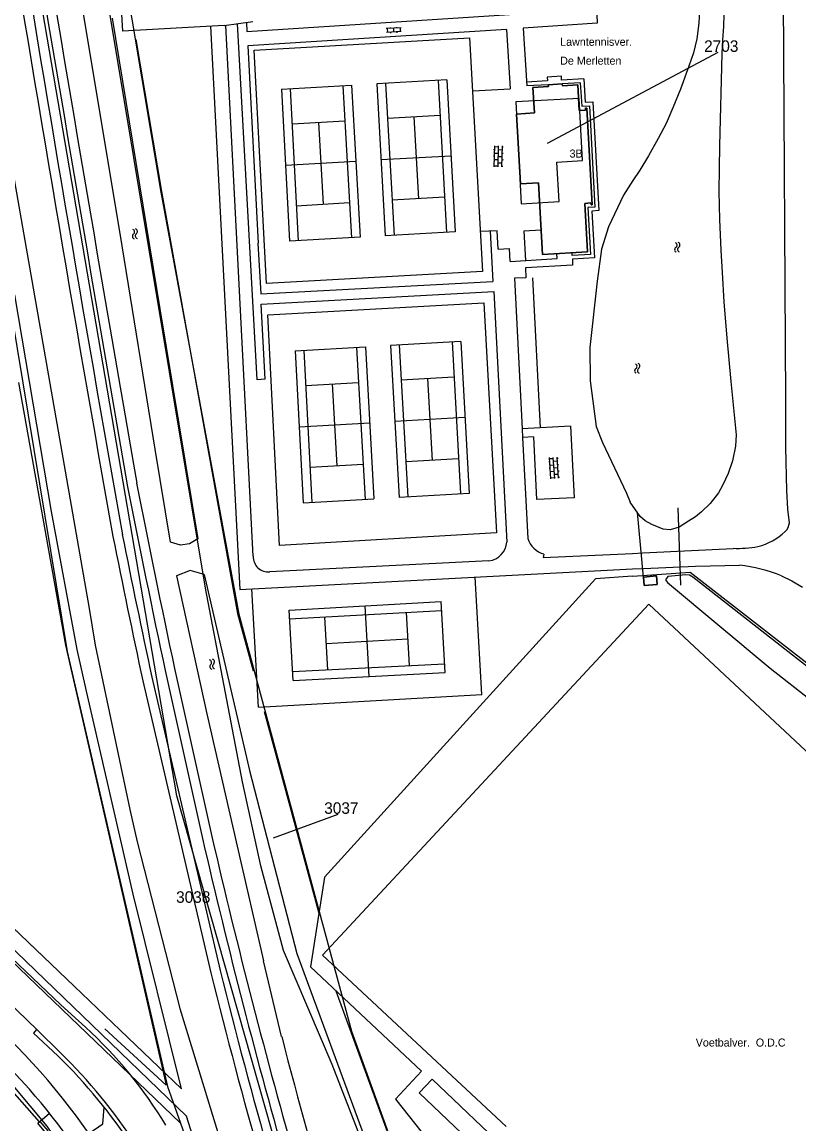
# Model space of a CAD drawing. Extents: x 148816 to 151297, y 399515 to 402500.
# Drawn here: x 149404.6 to 149526, y 400552.9 to 400725 of the extents above; entities that cross this region are included whole.
import ezdxf

# ---------------------------------------------------------------- set-up
doc = ezdxf.new("R2010")
doc.units = 0
for name, color, linetype in [('B01 Hoofdgebouw  [D] Norm', 7, 'Continuous'), ('B01 Hoofdgebouw  [T] Norm', 7, 'Continuous'), ('B01 hoofgebouw', 7, 'Continuous'), ('B03 Overig opstal  [D] Norm', 7, 'Continuous'), ('G01 perceelsgrens', 7, 'Continuous'), ('Q01 Spoorrail  [D] Norm', 7, 'Continuous'), ('Q21 Lichtmast  Gem', 7, 'Continuous'), ('S02 Open verharding  Norm', 7, 'Continuous'), ('S05 Water  Norm', 7, 'Continuous'), ('T01 Muur  [D] Gem', 7, 'Continuous'), ('T01 Muur  [T] Gem', 7, 'Continuous'), ('T04 Haag heg  [D] Gem', 7, 'Continuous'), ('T09 Insteek water  [T] Norm', 7, 'Continuous'), ('V00 Kant verharding algemeen  [T] Norm', 7, 'Continuous'), ('V00 Kant verharding algemeen secundair  [T] Gem', 7, 'Continuous'), ('V06 Kant onverhard  [T] Gem', 7, 'Continuous'), ('W10 Duiker  [T] Gem', 7, 'Continuous'), ('Z01 perceelnummer', 7, 'Continuous'), ('Z02 Huisnummer  [Tekst] Norm', 7, 'Continuous'), ('Z19 Overige Tekst  [Tekst] Gem', 7, 'Continuous')]:
    doc.layers.add(name, color=color, linetype=linetype)

msp = doc.modelspace()

# ---------------------------------------------------------------- linework, layer by layer
at = {"layer": 'B01 Hoofdgebouw  [D] Norm'}
msp.add_lwpolyline([(149468.7, 400559.93), (149477.56, 400551.5), (149475.54, 400549.38), (149466.68, 400557.81)], close=True, dxfattribs=at)
at = {"layer": 'B01 Hoofdgebouw  [T] Norm'}
for p, q in [((149492.98, 400689.1), (149485.94, 400688.7)), ((149503.76, 400638.51), (149501.71, 400638.32)), ((149501.71, 400638.32), (149501.83, 400637)), ((149503.88, 400637.19), (149503.76, 400638.51)), ((149501.83, 400637), (149503.88, 400637.19))]:
    msp.add_line(p, q, dxfattribs=at)
for points in [[(149492.87, 400711.54), (149492.65, 400711.53), (149492.67, 400711.24), (149491.69, 400711.18), (149491.46, 400715.16), (149489.05, 400715.02), (149489.03, 400715.32), (149486.86, 400715.2), (149486.88, 400714.9), (149484.45, 400714.76), (149484.68, 400710.79), (149481.88, 400710.62), (149482.5, 400699.73), (149485.3, 400699.89), (149485.94, 400688.7), (149492.98, 400689.1)], [(149485.94, 400688.7), (149492.98, 400689.1), (149492.54, 400696.67), (149493.52, 400696.73), (149493.54, 400696.44), (149493.72, 400696.45), (149492.87, 400711.54)]]:
    msp.add_lwpolyline(points, dxfattribs=at)
at = {"layer": 'B01 hoofgebouw'}
for points in [[(149491.69, 400711.18), (149492.67, 400711.24), (149492.67, 400711.59), (149492.87, 400711.54), (149493.72, 400696.45), (149493.54, 400696.44), (149493.52, 400696.73), (149492.54, 400696.67), (149492.98, 400689.1), (149485.94, 400688.7), (149485.3, 400699.89), (149482.5, 400699.73), (149481.88, 400710.62), (149484.68, 400710.79), (149484.45, 400714.76), (149486.88, 400714.9), (149486.86, 400715.2), (149489.03, 400715.32), (149489.05, 400715.02), (149491.46, 400715.16), (149491.69, 400711.18)], [(149501.71, 400638.32), (149503.76, 400638.51), (149503.88, 400637.19), (149501.83, 400637), (149501.71, 400638.32)]]:
    msp.add_lwpolyline(points, dxfattribs=at)
at = {"layer": 'B03 Overig opstal  [D] Norm'}
msp.add_line((149407.42, 400553.33), (149408.92, 400554.61), dxfattribs=at)
at = {"layer": 'G01 perceelsgrens'}
for points in [[(149474.3, 400500), (149465.62, 400529.89), (149453.09, 400562.24), (149445.47, 400580.02), (149441.93, 400593.24), (149439.07, 400606.36), (149433.29, 400636.6), (149410.86, 400771.43), (149399.43, 400842.23), (149379.26, 400968.4), (149379, 400970.86), (149375.68, 400970.26), (149373.64, 400982.49), (149377.7, 400983.23), (149377.26, 400987.35)], [(149380.85, 400976.67), (149402.17, 400842.5), (149426.33, 400698.43), (149438.5, 400632.51), (149456.12, 400567.45), (149480.52, 400500)], [(149492.2, 400703.36), (149491.67, 400713.05), (149481.76, 400712.51), (149482.63, 400696.62), (149488.56, 400696.97), (149488.2, 400703.12), (149492.2, 400703.36)], [(149401.28, 400689.77), (149411.69, 400626.68), (149427.38, 400558.77), (149429.39, 400553.07)], [(149347.22, 400631.91), (149429.39, 400553.07)], [(149403.2, 400558.96), (149408.53, 400552.62), (149411.03, 400548.92)], [(149429.39, 400553.07), (149448.02, 400500)]]:
    msp.add_lwpolyline(points, dxfattribs=at)
at = {"layer": 'Q01 Spoorrail  [D] Norm'}
for p, q in [((149424.93, 400622.69), (149435.58, 400576.88)), ((149427.01, 400623.72), (149432.83, 400597.5)), ((149428.47, 400624.05), (149434.3, 400597.83)), ((149423.52, 400622.14), (149434.12, 400576.52)), ((149401.92, 400559.42), (149407.33, 400553.28))]:
    msp.add_line(p, q, dxfattribs=at)
for centre, radius, start, end in [((156405.27, 401884.74), 7094.13, 189.218769, 190.064919), ((165820.47, 403491.79), 16643.33, 189.484339, 189.821758), ((165820.47, 403491.79), 16641.83, 189.485686, 189.821758), ((156405.27, 401884.74), 7095.63, 189.218769, 190.064919), ((151062.51, 400973.51), 1672.49, 191.05884, 192.0799), ((151062.51, 400973.51), 1670.99, 191.05884, 192.07174), ((150862.74, 400932.64), 1470.84, 191.27964, 192.16518), ((150862.74, 400932.64), 1472.34, 191.27964, 192.17434), ((150428.26, 400826.81), 1021.49, 192.97285, 195.97777), ((150428.26, 400826.81), 1019.99, 192.97285, 195.97777), ((150353.21, 400806.24), 947.36, 194.03323, 197.71533), ((150353.21, 400806.24), 945.86, 194.03323, 197.71533)]:
    msp.add_arc(centre, radius, start, end, dxfattribs=at)
at = {"layer": 'Q21 Lichtmast  Gem'}
msp.add_lwpolyline([(149831.23, 399977.82), (149652.8, 400166.23), (149577.93, 400264.8), (149509.93, 400379.6), (149457.52, 400503.12), (149428.83, 400604.19), (149365.19, 400976.02), (149329.8, 401182.82), (149252.91, 401632.09)], dxfattribs=at)
at = {"layer": 'S02 Open verharding  Norm'}
for p, q in [((149463.85, 400724.09), (149461.55, 400723.95)), ((149462.2, 400723.99), (149462.19, 400724.14)), ((149462.74, 400723.42), (149462.7, 400724.02)), ((149463.2, 400724.05), (149463.19, 400724.2)), ((149463.7, 400724.08), (149463.73, 400723.48)), ((149463.88, 400723.49), (149461.59, 400723.35)), ((149461.7, 400723.96), (149461.74, 400723.36)), ((149462.24, 400723.24), (149462.24, 400723.39)), ((149463.24, 400723.3), (149463.23, 400723.45)), ((149478.4, 400702.38), (149478.48, 400705.67)), ((149478.48, 400705.53), (149479.08, 400705.51)), ((149479.01, 400702.36), (149479.08, 400705.66)), ((149479.61, 400702.35), (149479.68, 400705.65)), ((149479.68, 400705.5), (149479.83, 400705.49)), ((149478.44, 400704.03), (149478.29, 400704.03)), ((149478.46, 400705.03), (149478.32, 400705.03)), ((149478.43, 400703.53), (149479.03, 400703.51)), ((149478.45, 400704.53), (149479.05, 400704.51)), ((149479.04, 400704.01), (149479.64, 400704)), ((149479.66, 400705), (149479.07, 400705.01)), ((149479.63, 400703.5), (149479.78, 400703.49)), ((149479.65, 400704.5), (149479.8, 400704.49)), ((149478.42, 400703.03), (149478.27, 400703.03)), ((149478.41, 400702.53), (149479.01, 400702.51)), ((149479.02, 400703.01), (149479.62, 400703)), ((149479.61, 400702.5), (149479.76, 400702.49)), ((149487.26, 400653.68), (149487.04, 400656.97)), ((149487.86, 400653.72), (149487.64, 400657.01)), ((149488.46, 400653.76), (149488.24, 400657.05)), ((149487.08, 400656.32), (149486.93, 400656.31)), ((149487.15, 400655.32), (149487, 400655.31)), ((149487.05, 400656.82), (149487.65, 400656.86)), ((149487.12, 400655.82), (149487.72, 400655.86)), ((149488.28, 400656.4), (149487.68, 400656.36)), ((149487.75, 400655.36), (149488.35, 400655.41)), ((149488.25, 400656.9), (149488.4, 400656.91)), ((149488.32, 400655.91), (149488.46, 400655.92)), ((149487.22, 400654.33), (149487.07, 400654.32)), ((149487.18, 400654.83), (149487.78, 400654.87)), ((149487.25, 400653.83), (149487.85, 400653.87)), ((149487.82, 400654.37), (149488.42, 400654.41)), ((149488.38, 400654.91), (149488.53, 400654.92)), ((149488.45, 400653.91), (149488.6, 400653.92))]:
    msp.add_line(p, q, dxfattribs=at)
at = {"layer": 'S05 Water  Norm'}
for centre, start, end in [((149422.31, 400691.53), 126.4891, 250.3441), ((149421.81, 400692.21), 306.4891, 70.3441), ((149422.76, 400691.6), 126.4891, 250.3441), ((149422.25, 400692.28), 306.4891, 70.3441), ((149507.02, 400689.43), 123.6187, 247.4737), ((149506.55, 400690.14), 303.6187, 67.4737), ((149507.47, 400689.47), 123.6187, 247.4737), ((149507, 400690.18), 303.6187, 67.4737), ((149500.77, 400670.53), 123.6187, 247.4737), ((149500.29, 400671.23), 303.6187, 67.4737), ((149501.21, 400670.57), 123.6187, 247.4737), ((149500.74, 400671.28), 303.6187, 67.4737), ((149433.84, 400624.99), 310.7816, 74.6367), ((149434.39, 400624.34), 130.7816, 254.6367), ((149434.28, 400625.09), 310.7816, 74.6367), ((149434.83, 400624.44), 130.7816, 254.6367)]:
    msp.add_arc(centre, 0.425, start, end, dxfattribs=at)
at = {"layer": 'T01 Muur  [D] Gem'}
msp.add_line((149490.92, 400650.68), (149485.03, 400650.42), dxfattribs=at)
at = {"layer": 'T01 Muur  [T] Gem'}
msp.add_lwpolyline([(149407.42, 400553.33), (149408.68, 400551.86), (149408.36, 400551.58), (149407.1, 400553.05)], close=True, dxfattribs=at)
at = {"layer": 'T04 Haag heg  [D] Gem'}
for p, q in [((149418.3, 400760.19), (149420.33, 400723.57)), ((149493.36, 400750), (149494.49, 400724.81)), ((149436.21, 400724.45), (149420.33, 400723.57)), ((149436.21, 400724.45), (149440.71, 400725.05)), ((149422.44, 400722.26), (149426.42, 400698.53)), ((149426.42, 400698.53), (149438.31, 400632.66)), ((149484.39, 400685.05), (149485.56, 400661.62)), ((149404.1, 400668.72), (149411.41, 400627.67)), ((149501.71, 400638.32), (149500.79, 400648.43)), ((149494.21, 400638.03), (149451.92, 400591.46)), ((149476.49, 400619.99), (149475.45, 400638.32)), ((149500, 400638.49), (149494.21, 400638.03)), ((149441.6, 400618), (149440.54, 400636.51)), ((149438.31, 400632.66), (149440.76, 400623.67)), ((149411.41, 400627.67), (149427.16, 400558.98)), ((149441.6, 400618), (149476.49, 400619.99)), ((149442.47, 400617.36), (149451.03, 400585.85)), ((149451.92, 400591.46), (149449.7, 400577.45)), ((149449.7, 400577.45), (149467.04, 400561.2)), ((149453.67, 400573.73), (149466.1, 400539.69)), ((149427.16, 400558.98), (149417.6, 400567.79)), ((149467.04, 400561.2), (149462.98, 400556.79)), ((149462.98, 400556.79), (149472.31, 400545.12))]:
    msp.add_line(p, q, dxfattribs=at)
for points in [[(149440.91, 400720.59), (149474.55, 400722.49), (149476.6, 400686.04), (149442.82, 400684.14)], [(149443.05, 400679.25), (149476.81, 400681.16), (149478.76, 400645.21), (149444.85, 400643.28)]]:
    msp.add_lwpolyline(points, close=True, dxfattribs=at)
msp.add_lwpolyline([(149500.04, 400638.49), (149509, 400639.11), (149576.33, 400586.78), (149574.66, 400584.2)], dxfattribs=at)
at = {"layer": 'T09 Insteek water  [T] Norm'}
for p, q in [((149394.73, 400749.75), (149409, 400668.53)), ((149420.27, 400690.04), (149414.18, 400726.64)), ((149418.7, 400725.56), (149426.17, 400680.22)), ((149500.06, 400700.24), (149498.6, 400697.95)), ((149498.6, 400697.95), (149496.27, 400692.98)), ((149496.27, 400692.98), (149495.18, 400689.53)), ((149425.46, 400658.28), (149420.27, 400690.04)), ((149495.18, 400689.53), (149494.48, 400684.54)), ((149494.48, 400684.54), (149493.35, 400674.18)), ((149409.23, 400648.57), (149403.52, 400682.4)), ((149426.17, 400680.22), (149432.13, 400644.28)), ((149493.35, 400674.18), (149493.4, 400668.96)), ((149493.4, 400668.96), (149494.33, 400661.85)), ((149409, 400668.53), (149415.13, 400633.42)), ((149494.33, 400661.85), (149495.3, 400659.36)), ((149495.3, 400659.36), (149499.09, 400651.41)), ((149427.86, 400643.79), (149425.46, 400658.28)), ((149499.09, 400651.41), (149499.65, 400650.04)), ((149413.24, 400627.01), (149409.23, 400648.57)), ((149429.41, 400643.32), (149427.86, 400643.79)), ((149430.81, 400643.52), (149429.41, 400643.32)), ((149432.13, 400644.28), (149430.81, 400643.52)), ((149430.89, 400639.34), (149428.76, 400638.53)), ((149428.76, 400638.53), (149433.53, 400616.95)), ((149433.08, 400638.73), (149430.89, 400639.34)), ((149433.08, 400638.73), (149440.17, 400608.14)), ((149415.13, 400633.42), (149416.08, 400627.72)), ((149416.08, 400627.72), (149421.49, 400602.04)), ((149414.69, 400620.53), (149413.24, 400627.01)), ((149361.72, 400620.3), (149430.31, 400554.17)), ((149365.07, 400619.97), (149429.54, 400558.45)), ((149421.99, 400588.82), (149414.69, 400620.53)), ((149433.53, 400616.95), (149438.23, 400596.33)), ((149440.17, 400608.14), (149447.56, 400579.54)), ((149421.49, 400602.04), (149422.62, 400596.98)), ((149422.62, 400596.98), (149429.27, 400570.97)), ((149438.23, 400596.33), (149442.34, 400578.42)), ((149429.54, 400558.45), (149421.99, 400588.82)), ((149447.56, 400579.54), (149462.1, 400540.25)), ((149445.2, 400566.58), (149442.34, 400578.42)), ((149429.27, 400570.97), (149435.57, 400550.43)), ((149445.11, 400508.66), (149430.31, 400554.17))]:
    msp.add_line(p, q, dxfattribs=at)
for points in [[(149500.11, 400741.27), (149501.96, 400739.77), (149504.86, 400737.09), (149507.34, 400734.15), (149508.99, 400731.55), (149510.06, 400729.18), (149510.47, 400726.87), (149510.37, 400724.79), (149510.04, 400722.35), (149509.53, 400720.19), (149508.8, 400718.07), (149507.49, 400714.48), (149506.31, 400711.6), (149505.27, 400709.12), (149504.03, 400706.78), (149502.51, 400704.07), (149501.14, 400701.87), (149500.07, 400700.23)], [(149514.29, 400726.13), (149514.23, 400724.3), (149514.05, 400722.2), (149513.95, 400720.01), (149513.59, 400705.67), (149513.53, 400702.14), (149513.52, 400698.54), (149513.6, 400694.17), (149513.81, 400689.36), (149514.01, 400685.88), (149514.29, 400681.29), (149514.76, 400675.61), (149515.38, 400668.85), (149516.21, 400660.53), (149516.08, 400658.75), (149515.65, 400656.49), (149514.96, 400654.48), (149514.14, 400652.74), (149513.42, 400651.47), (149512.12, 400649.8), (149510.79, 400648.49), (149509.86, 400647.74), (149508.75, 400647.04), (149507.29, 400646.14), (149505.9, 400645.72), (149504.78, 400645.81), (149503.05, 400646.55), (149501.97, 400647.09), (149501.2, 400647.79), (149499.65, 400650.04)], [(149505.46, 400637.47), (149521.52, 400624.1), (149541.05, 400608.8), (149573.02, 400583.9), (149573.6, 400583.81), (149574.13, 400584.09), (149575.61, 400585.93), (149575.75, 400586.55), (149575.39, 400586.95), (149547.4, 400608.72), (149525.49, 400625.75), (149509.44, 400638.32), (149508.93, 400638.62), (149508.35, 400638.69), (149505.51, 400638.41), (149505.18, 400637.92), (149505.46, 400637.47)]]:
    msp.add_lwpolyline(points, dxfattribs=at)
msp.add_arc((150197.18, 400759.81), 776.4, 194.41109, 199.00678, dxfattribs=at)
at = {"layer": 'V00 Kant verharding algemeen  [T] Norm'}
for p, q in [((149523.97, 400665.97), (149523.48, 400750)), ((149439.77, 400723.48), (149492.88, 400726.92)), ((149434.07, 400724.33), (149438.69, 400636.41)), ((149440.76, 400641.58), (149436.48, 400724.46)), ((149439.69, 400724.91), (149439.77, 400723.48)), ((149494.49, 400724.81), (149482.93, 400724)), ((149480.32, 400723.79), (149439.93, 400721.27)), ((149480.31, 400723.83), (149480.89, 400714.57)), ((149482.93, 400724), (149483.49, 400715.01)), ((149439.93, 400721.27), (149441.51, 400690.47)), ((149471.03, 400715.95), (149460.05, 400715.33)), ((149469.66, 400715.87), (149470.96, 400692.14)), ((149471.03, 400715.95), (149472.33, 400692.21)), ((149491.86, 400715.48), (149489.03, 400715.32)), ((149445.16, 400714.49), (149456.12, 400715.11)), ((149445.16, 400714.49), (149446.41, 400690.75)), ((149446.53, 400714.56), (149447.77, 400690.83)), ((149454.75, 400715.03), (149456.09, 400691.3)), ((149456.12, 400715.11), (149457.46, 400691.37)), ((149460.05, 400715.33), (149461.39, 400691.6)), ((149461.42, 400715.4), (149462.76, 400691.67)), ((149486.86, 400715.2), (149483.49, 400715.01)), ((149469.96, 400710.39), (149461.73, 400709.92)), ((149446.82, 400709.08), (149455.06, 400709.55)), ((149450.95, 400709.31), (149451.67, 400696.55)), ((149465.85, 400710.16), (149466.57, 400697.39)), ((149471.68, 400704.05), (149460.72, 400703.45)), ((149445.78, 400702.63), (149456.79, 400703.24)), ((149447.49, 400696.31), (149455.78, 400696.78)), ((149470.66, 400697.62), (149462.45, 400697.15)), ((149457.46, 400691.37), (149446.41, 400690.75)), ((149472.33, 400692.21), (149461.39, 400691.6)), ((149441.5, 400690.47), (149441.96, 400682.57)), ((149479.03, 400689.52), (149480.8, 400689.61)), ((149480.88, 400687.58), (149480.8, 400689.61)), ((149490.6, 400688.55), (149490.57, 400688.97)), ((149441.96, 400682.57), (149478.19, 400684.49)), ((149481.59, 400685.01), (149482.77, 400661.48)), ((149442.01, 400680.95), (149478.36, 400682.91)), ((149478.36, 400682.91), (149480.36, 400643.79)), ((149442.62, 400669.2), (149442.01, 400680.95)), ((149447.33, 400673.65), (149458.28, 400674.27)), ((149456.91, 400674.19), (149458.25, 400650.46)), ((149458.28, 400674.27), (149459.62, 400650.54)), ((149473.19, 400675.11), (149462.21, 400674.49)), ((149462.21, 400674.49), (149463.55, 400650.76)), ((149463.58, 400674.57), (149464.92, 400650.84)), ((149471.82, 400675.04), (149473.12, 400651.3)), ((149473.19, 400675.11), (149474.49, 400651.38)), ((149447.33, 400673.65), (149448.57, 400649.92)), ((149448.69, 400673.72), (149449.94, 400649.99)), ((149472.12, 400669.55), (149463.89, 400669.09)), ((149468.01, 400669.32), (149468.73, 400656.55)), ((149448.98, 400668.25), (149457.22, 400668.71)), ((149453.11, 400668.48), (149453.83, 400655.71)), ((149523.95, 400658.61), (149523.97, 400665.97)), ((149447.95, 400661.8), (149458.95, 400662.4)), ((149473.84, 400663.22), (149462.88, 400662.62)), ((149490.35, 400661.86), (149490.92, 400650.68)), ((149484.53, 400660.2), (149482.85, 400660.11)), ((149482.85, 400660.11), (149483.65, 400644.37)), ((149484.53, 400660.2), (149485.03, 400650.42)), ((149524.11, 400651.83), (149523.95, 400658.61)), ((149449.65, 400655.48), (149457.94, 400655.94)), ((149472.82, 400656.78), (149464.61, 400656.32)), ((149524.3, 400648.94), (149524.11, 400651.83)), ((149448.57, 400649.92), (149459.62, 400650.54)), ((149474.49, 400651.38), (149463.55, 400650.76)), ((149524.54, 400646.78), (149524.3, 400648.94)), ((149500, 400642.02), (149501.61, 400642.09)), ((149501.61, 400642.09), (149515.73, 400642.81)), ((149477.57, 400640.88), (149443.36, 400639.15)), ((149501.75, 400639.68), (149509.84, 400640.05)), ((149509.84, 400640.05), (149516.73, 400640.18)), ((149438.69, 400636.41), (149500, 400639.59)), ((149500, 400639.59), (149501.75, 400639.68)), ((149523.3, 400638.53), (149524.91, 400637.74)), ((149524.91, 400637.74), (149526.59, 400636.75)), ((149446.38, 400633.15), (149470.11, 400634.49)), ((149446.99, 400622.19), (149446.38, 400633.15)), ((149446.45, 400631.78), (149470.18, 400633.12)), ((149458.85, 400622.81), (149458.24, 400633.82)), ((149470.73, 400623.44), (149470.11, 400634.49)), ((149452.4, 400623.85), (149451.93, 400632.09)), ((149465.17, 400624.52), (149464.7, 400632.81)), ((149452.17, 400627.98), (149464.93, 400628.7)), ((149446.92, 400623.56), (149470.66, 400624.8)), ((149446.99, 400622.19), (149470.73, 400623.44)), ((149410.72, 400571.52), (149381.16, 400599.65)), ((149377.89, 400595.57), (149407.02, 400567.62)), ((149414.56, 400568.08), (149410.72, 400571.52)), ((149406.9, 400567.68), (149406.43, 400567.11)), ((149407.02, 400567.62), (149410.65, 400564.03)), ((149410.22, 400563.58), (149406.43, 400567.11))]:
    msp.add_line(p, q, dxfattribs=at)
for points in [[(149442.62, 400669.2), (149441.37, 400669.14), (149438.3, 400724.73)], [(149492.43, 400716.11), (149492.63, 400712.47), (149493.83, 400712.51), (149494.73, 400695.54), (149493.67, 400695.46), (149494.07, 400688.14), (149490.63, 400687.95), (149490.65, 400687.04), (149483.3, 400686.62), (149483.33, 400685.03), (149481.59, 400685.01)], [(149492.43, 400716.11), (149488.93, 400715.92), (149488.9, 400716.52), (149486.7, 400716.39), (149486.74, 400715.79), (149483.45, 400715.61)], [(149491.86, 400715.48), (149492.07, 400711.84), (149493.27, 400711.89), (149494.1, 400696.1), (149493.04, 400696.02), (149493.44, 400688.71), (149490.6, 400688.55)], [(149485.73, 400692.48), (149483.01, 400692.33), (149483.27, 400687.73)], [(149480.88, 400687.58), (149488.22, 400688.05), (149488.17, 400688.83)], [(149486.18, 400641.92), (149486.03, 400641.39), (149500, 400642.02)], [(149534.45, 400502.05), (149585.36, 400556.83), (149502.54, 400634.12), (149451.56, 400579.29), (149480.3, 400552.55)], [(149392.39, 400572.21), (149400.08, 400564.48), (149405.8, 400558.36), (149405.8, 400558.36)], [(149415.09, 400551.45), (149417.28, 400552.97), (149417.46, 400555.59)]]:
    msp.add_lwpolyline(points, dxfattribs=at)
for centre, radius, start, end in [((149522.1, 400647.16), 2.47, 315.4259, 351.105), ((149517.25, 400652.41), 9.61, 284.1295, 313.4301), ((149516.4, 400660.47), 17.67, 267.8356, 280.4408), ((149514.1, 400615.82), 24.5, 67.957, 83.8474), ((149366.03, 400515.47), 71.57, 31.39, 47.3108), ((149329.01, 400491.58), 104.85, 14.1497, 45.4704), ((149352.69, 400504.21), 83.29, 33.0688, 45.9041), ((149352.69, 400504.21), 82.67, 33.0688, 45.9041), ((149330.5, 400492.59), 99.98, 15.5421, 41.1391)]:
    msp.add_arc(centre, radius, start, end, dxfattribs=at)
at = {"layer": 'V00 Kant verharding algemeen secundair  [T] Gem'}
msp.add_line((149482.77, 400661.48), (149482.85, 400660.11), dxfattribs=at)
at = {"layer": 'V06 Kant onverhard  [T] Gem'}
for p, q in [((149475.06, 400714.25), (149480.89, 400714.57)), ((149478.89, 400692.39), (149476.27, 400692.26)), ((149477.76, 400692.32), (149478.18, 400684.48)), ((149479.03, 400689.52), (149478.89, 400692.39)), ((149479.05, 400689.52), (149479.01, 400689.52)), ((149490.35, 400661.86), (149482.77, 400661.48))]:
    msp.add_line(p, q, dxfattribs=at)
for centre, radius, start, end in [((149477.28, 400643.96), 3.09, 275.5054, 357.0255), ((149487.18, 400645.48), 3.69, 197.4976, 254.2893), ((149443.11, 400641.48), 2.35, 177.6575, 276.0598)]:
    msp.add_arc(centre, radius, start, end, dxfattribs=at)
at = {"layer": 'W10 Duiker  [T] Gem'}
msp.add_line((149507.08, 400649.16), (149507.53, 400637.07), dxfattribs=at)
at = {"layer": 'Z01 perceelnummer'}
for points in [[(149513.32, 400720.22), (149486.68, 400706.01)], [(149453.98, 400601.26), (149443.85, 400597.58)]]:
    msp.add_lwpolyline(points, dxfattribs=at)

# ---------------------------------------------------------------- texts
for s, p in [('2703', (149511.2, 400720.32)), ('3037', (149451.85, 400601.36)), ('3038', (149428.71, 400587.47))]:
    msp.add_text(s, height=1.8, dxfattribs=at).set_placement(p)
at = {"layer": 'Z02 Huisnummer  [Tekst] Norm'}
msp.add_text('3B', height=1.25, dxfattribs=at).set_placement((149490.18, 400703.82))
at = {"layer": 'Z19 Overige Tekst  [Tekst] Gem'}
for s, p in [('Lawntennisver.', (149488.71, 400721.27)), ('De Merletten', (149488.71, 400718.32)), ('Voetbalver.  O.D.C', (149509.89, 400565.03))]:
    msp.add_text(s, height=1.25, rotation=360, dxfattribs=at).set_placement(p)

doc.saveas('drawing.dxf')
